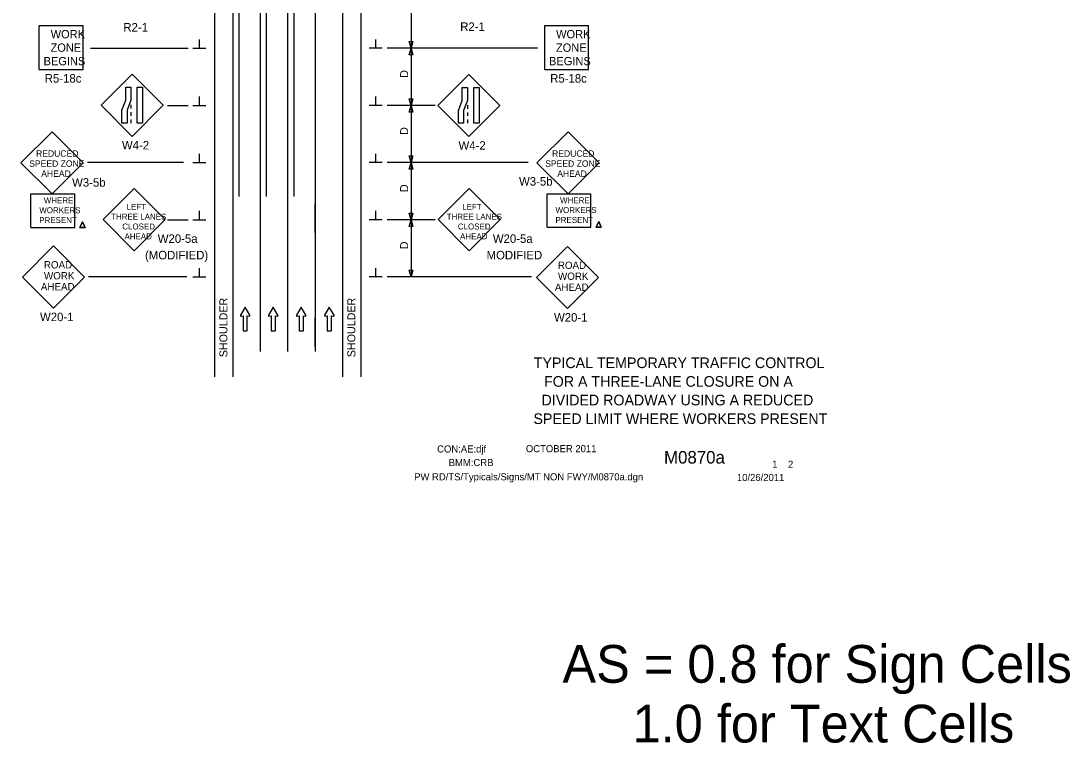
# Model space of a CAD drawing. Extents: x 16727 to 18475, y 5704 to 7011.
# Drawn here: x 16727 to 17644, y 5704 to 6336 of the extents above; entities that cross this region are included whole.
import ezdxf

# ---------------------------------------------------------------- set-up
doc = ezdxf.new("R2010")
doc.units = 0
for name, color, linetype in [('ALI_LEGAL_EX', 7, 'Continuous'), ('BORDER', 7, 'Continuous'), ('BORDER_SIGNAL_WO', 7, 'Continuous'), ('MT_SCRATCH_LEVEL_E', 7, 'Continuous'), ('PAVT_EDGE_EX', 7, 'Continuous'), ('TRAFFIC_SIGNS_PR', 7, 'Continuous'), ('TYPICAL_TEXT_DIMEN_PR', 7, 'Continuous')]:
    doc.layers.add(name, color=color, linetype=linetype)

msp = doc.modelspace()

# ---------------------------------------------------------------- linework, layer by layer
at = {"layer": 'ALI_LEGAL_EX'}
for p, q in [((16917.23, 7011.11), (16917.23, 6181.92)), ((16941.23, 7011.11), (16941.23, 6181.92)), ((16965.23, 7011.11), (16965.23, 6181.92)), ((16965.23, 7011.11), (16965.23, 6181.92)), ((16935.85, 6875.49), (16935.85, 6046.3)), ((16959.85, 6875.49), (16959.85, 6046.3)), ((16983.85, 6875.49), (16983.85, 6046.3)), ((16983.85, 6875.49), (16983.85, 6046.3))]:
    msp.add_line(p, q, dxfattribs=at)
for points in [[(16935.85, 6275.49), (16935.85, 6250.49)], [(16959.85, 6275.49), (16959.85, 6250.49)], [(16983.85, 6275.49), (16983.85, 6250.49)], [(16935.85, 6175.49), (16935.85, 6150.49)], [(16959.85, 6175.49), (16959.85, 6150.49)], [(16983.85, 6150.49), (16983.85, 6175.49)], [(16983.85, 6175.49), (16983.85, 6150.49)], [(16935.85, 6075.48), (16935.85, 6050.48)], [(16959.85, 6075.48), (16959.85, 6050.48)], [(16983.85, 6050.48), (16983.85, 6075.48)], [(16983.85, 6075.48), (16983.85, 6050.48)]]:
    msp.add_lwpolyline(points, dxfattribs=at)
at = {"layer": 'MT_SCRATCH_LEVEL_E'}
for p, q in [((16922.76, 6085.3), (16918.65, 6078.06)), ((16922.76, 6085.3), (16918.65, 6078.06)), ((16926.91, 6078.06), (16922.76, 6085.3)), ((16926.91, 6078.06), (16922.76, 6085.3)), ((16947.29, 6085.3), (16943.18, 6078.06)), ((16947.29, 6085.3), (16943.18, 6078.06)), ((16951.44, 6078.06), (16947.29, 6085.3)), ((16951.44, 6078.06), (16947.29, 6085.3)), ((16971.82, 6085.3), (16967.71, 6078.06)), ((16971.82, 6085.3), (16967.71, 6078.06)), ((16975.97, 6078.06), (16971.82, 6085.3)), ((16975.97, 6078.06), (16971.82, 6085.3)), ((16996.38, 6085.3), (16992.27, 6078.06)), ((16996.38, 6085.3), (16992.27, 6078.06)), ((17000.53, 6078.06), (16996.38, 6085.3)), ((17000.53, 6078.06), (16996.38, 6085.3)), ((16919.14, 6077.38), (16920.91, 6077.69)), ((16919.14, 6077.38), (16920.91, 6077.69)), ((16920.91, 6077.69), (16920.91, 6064.44)), ((16920.91, 6077.69), (16920.91, 6064.44)), ((16924.65, 6064.44), (16924.65, 6077.69)), ((16924.65, 6077.69), (16926.43, 6077.38)), ((16924.65, 6064.44), (16924.65, 6077.69)), ((16924.65, 6077.69), (16926.43, 6077.38)), ((16943.67, 6077.38), (16945.44, 6077.69)), ((16943.67, 6077.38), (16945.44, 6077.69)), ((16945.44, 6077.69), (16945.44, 6064.44)), ((16945.44, 6077.69), (16945.44, 6064.44)), ((16949.18, 6064.44), (16949.18, 6077.69)), ((16949.18, 6077.69), (16950.96, 6077.38)), ((16949.18, 6064.44), (16949.18, 6077.69)), ((16949.18, 6077.69), (16950.96, 6077.38)), ((16968.19, 6077.38), (16969.97, 6077.69)), ((16968.19, 6077.38), (16969.97, 6077.69)), ((16969.97, 6077.69), (16969.97, 6064.44)), ((16969.97, 6077.69), (16969.97, 6064.44)), ((16973.71, 6064.44), (16973.71, 6077.69)), ((16973.71, 6077.69), (16975.49, 6077.38)), ((16973.71, 6064.44), (16973.71, 6077.69)), ((16973.71, 6077.69), (16975.49, 6077.38)), ((16992.75, 6077.38), (16994.53, 6077.69)), ((16992.75, 6077.38), (16994.53, 6077.69)), ((16994.53, 6077.69), (16994.53, 6064.44)), ((16994.53, 6077.69), (16994.53, 6064.44)), ((16998.27, 6064.44), (16998.27, 6077.69)), ((16998.27, 6077.69), (17000.05, 6077.38)), ((16998.27, 6064.44), (16998.27, 6077.69)), ((16998.27, 6077.69), (17000.05, 6077.38)), ((16920.91, 6064.44), (16924.65, 6064.44)), ((16920.91, 6064.44), (16924.65, 6064.44)), ((16945.44, 6064.44), (16949.18, 6064.44)), ((16945.44, 6064.44), (16949.18, 6064.44)), ((16969.97, 6064.44), (16973.71, 6064.44)), ((16969.97, 6064.44), (16973.71, 6064.44)), ((16994.53, 6064.44), (16998.27, 6064.44)), ((16994.53, 6064.44), (16998.27, 6064.44))]:
    msp.add_line(p, q, dxfattribs=at)
for centre, start, end in [((16919.06, 6077.84), 150.42484, 279.96381), ((16919.06, 6077.84), 150.42484, 279.96381), ((16926.5, 6077.84), 260.03619, 29.77312), ((16926.5, 6077.84), 260.03619, 29.77312), ((16943.59, 6077.84), 150.42484, 279.96381), ((16943.59, 6077.84), 150.42484, 279.96381), ((16951.03, 6077.84), 260.03619, 29.77312), ((16951.03, 6077.84), 260.03619, 29.77312), ((16968.12, 6077.84), 150.42484, 279.96381), ((16968.12, 6077.84), 150.42484, 279.96381), ((16975.56, 6077.84), 260.03619, 29.77312), ((16975.56, 6077.84), 260.03619, 29.77312), ((16992.68, 6077.84), 150.42484, 279.96381), ((16992.68, 6077.84), 150.42484, 279.96381), ((17000.12, 6077.84), 260.03619, 29.77312), ((17000.12, 6077.84), 260.03619, 29.77312)]:
    msp.add_arc(centre, 0.463, start, end, dxfattribs=at)
at = {"layer": 'PAVT_EDGE_EX'}
for p, q in [((16911.85, 6920.73), (16911.85, 6024.13)), ((17007.85, 6920.73), (17007.85, 6024.13)), ((17023.85, 6920.73), (17023.85, 6024.13)), ((16895.85, 6869.12), (16895.85, 6024.13))]:
    msp.add_line(p, q, dxfattribs=at)
at = {"layer": 'TRAFFIC_SIGNS_PR'}
for p, q in [((16742.62, 6293.05), (16742.62, 6331.45)), ((16742.62, 6331.45), (16781.02, 6331.45)), ((16781.02, 6293.05), (16781.02, 6331.45)), ((17184.76, 6293.05), (17184.76, 6331.45)), ((17184.76, 6331.45), (17223.16, 6331.45)), ((17223.16, 6293.05), (17223.16, 6331.45)), ((16742.62, 6293.05), (16781.02, 6293.05)), ((16824, 6288.91), (16796.85, 6261.76)), ((16851.15, 6261.76), (16824, 6288.91)), ((17118.43, 6288.67), (17091.28, 6261.52)), ((17145.59, 6261.52), (17118.43, 6288.67)), ((17184.76, 6293.05), (17223.16, 6293.05)), ((16796.85, 6261.76), (16824, 6234.6)), ((16822.75, 6262.25), (16822.75, 6259.05)), ((16824, 6234.6), (16851.15, 6261.76)), ((17091.28, 6261.52), (17118.43, 6234.36)), ((17117.19, 6262.01), (17117.19, 6258.81)), ((17118.43, 6234.36), (17145.59, 6261.52)), ((16822.75, 6255.85), (16822.75, 6252.65)), ((16822.75, 6249.45), (16822.75, 6246.25)), ((17117.19, 6255.61), (17117.19, 6252.41)), ((17117.19, 6249.21), (17117.19, 6246.01)), ((16753.8, 6238.6), (16726.65, 6211.45)), ((16780.95, 6211.45), (16753.8, 6238.6)), ((17205.17, 6238.6), (17178.02, 6211.45)), ((17232.32, 6211.45), (17205.17, 6238.6)), ((16726.65, 6211.45), (16753.8, 6184.3)), ((16753.8, 6184.3), (16780.95, 6211.45)), ((17178.02, 6211.45), (17205.17, 6184.3)), ((17205.17, 6184.3), (17232.32, 6211.45)), ((16825.6, 6188.88), (16798.45, 6161.73)), ((16852.75, 6161.73), (16825.6, 6188.88)), ((17118.73, 6188.88), (17091.58, 6161.73)), ((17145.88, 6161.73), (17118.73, 6188.88)), ((16735.31, 6184.32), (16773.71, 6184.32)), ((16735.31, 6155), (16735.31, 6184.32)), ((16773.71, 6155), (16773.71, 6184.32)), ((17186.87, 6184.42), (17225.27, 6184.42)), ((17186.87, 6155.1), (17186.87, 6184.42)), ((17225.27, 6155.1), (17225.27, 6184.42)), ((16798.45, 6161.73), (16825.6, 6134.58)), ((16825.6, 6134.58), (16852.75, 6161.73)), ((17091.58, 6161.73), (17118.73, 6134.58)), ((17118.73, 6134.58), (17145.88, 6161.73)), ((16735.31, 6155), (16773.71, 6155)), ((17186.87, 6155.1), (17225.27, 6155.1)), ((16755.1, 6138.7), (16727.95, 6111.54)), ((16782.26, 6111.54), (16755.1, 6138.7)), ((17204.74, 6138.28), (17177.58, 6111.12)), ((17231.89, 6111.12), (17204.74, 6138.28)), ((16727.95, 6111.54), (16755.1, 6084.39)), ((16755.1, 6084.39), (16782.26, 6111.54)), ((17177.58, 6111.12), (17204.74, 6083.97)), ((17204.74, 6083.97), (17231.89, 6111.12))]:
    msp.add_line(p, q, dxfattribs=at)
for points in [[(16822.75, 6277.49), (16822.75, 6266.31), (16819.41, 6257.43), (16819.41, 6246.25), (16814.92, 6246.25), (16814.92, 6257.43), (16818.26, 6266.31), (16818.26, 6277.49)], [(16832.89, 6277.49), (16832.89, 6246.25), (16828.4, 6246.25), (16828.4, 6277.49)], [(17117.19, 6277.25), (17117.19, 6266.07), (17113.84, 6257.19), (17113.84, 6246.01), (17109.35, 6246.01), (17109.35, 6257.19), (17112.69, 6266.07), (17112.69, 6277.25)], [(17127.32, 6277.25), (17127.32, 6246.01), (17122.83, 6246.01), (17122.83, 6277.25)]]:
    msp.add_lwpolyline(points, close=True, dxfattribs=at)
for points in [[(16780.46, 6159.94), (16778.22, 6155)], [(16778.22, 6155), (16780.46, 6159.94)], [(16782.69, 6155), (16780.46, 6159.94)], [(16780.46, 6159.94), (16782.69, 6155)], [(17232.02, 6160.04), (17229.79, 6155.1)], [(17229.79, 6155.1), (17232.02, 6160.04)], [(17234.26, 6155.1), (17232.02, 6160.04)], [(17232.02, 6160.04), (17234.26, 6155.1)], [(16778.22, 6155), (16782.69, 6155)], [(16782.69, 6155), (16778.22, 6155)], [(17229.79, 6155.1), (17234.26, 6155.1)], [(17234.26, 6155.1), (17229.79, 6155.1)]]:
    msp.add_lwpolyline(points, dxfattribs=at)
at = {"layer": 'TYPICAL_TEXT_DIMEN_PR'}
for p, q in [((17067.85, 6361.65), (17067.85, 6311.65)), ((16882.73, 6311.65), (16882.73, 6319.43)), ((17036.98, 6311.65), (17036.98, 6319.43)), ((17067.85, 6311.65), (17066.28, 6317.51)), ((17066.28, 6317.51), (17067.85, 6317.51)), ((17067.85, 6317.51), (17069.42, 6317.51)), ((17069.42, 6317.51), (17067.85, 6311.65)), ((16787.54, 6311.65), (16872.85, 6311.65)), ((16877.1, 6311.65), (16888.35, 6311.65)), ((17042.6, 6311.65), (17031.35, 6311.65)), ((17178.58, 6311.65), (17046.85, 6311.65)), ((17066.28, 6305.79), (17067.85, 6311.65)), ((17067.85, 6305.79), (17066.28, 6305.79)), ((17067.85, 6311.65), (17069.42, 6305.79)), ((17067.85, 6311.65), (17067.85, 6261.65)), ((17069.42, 6305.79), (17067.85, 6305.79)), ((16882.73, 6261.65), (16882.73, 6269.43)), ((17036.98, 6261.65), (17036.98, 6269.43)), ((16854.78, 6261.65), (16872.85, 6261.65)), ((16877.1, 6261.65), (16888.35, 6261.65)), ((17042.6, 6261.65), (17031.35, 6261.65)), ((17089.07, 6261.65), (17046.85, 6261.65)), ((17067.85, 6261.65), (17066.28, 6267.51)), ((17066.28, 6267.51), (17067.85, 6267.51)), ((17066.28, 6255.79), (17067.85, 6261.65)), ((17067.85, 6267.51), (17069.42, 6267.51)), ((17069.42, 6267.51), (17067.85, 6261.65)), ((17067.85, 6261.65), (17067.85, 6211.65)), ((17067.85, 6261.65), (17069.42, 6255.79)), ((17067.85, 6255.79), (17066.28, 6255.79)), ((17069.42, 6255.79), (17067.85, 6255.79)), ((16882.73, 6211.65), (16882.73, 6219.43)), ((17036.98, 6211.65), (17036.98, 6219.43)), ((17067.85, 6211.65), (17066.28, 6217.51)), ((17066.28, 6217.51), (17067.85, 6217.51)), ((17067.85, 6217.51), (17069.42, 6217.51)), ((17069.42, 6217.51), (17067.85, 6211.65)), ((16868.8, 6211.65), (16784.7, 6211.65)), ((16877.1, 6211.65), (16888.35, 6211.65)), ((17042.6, 6211.65), (17031.35, 6211.65)), ((17170.25, 6211.65), (17046.85, 6211.65)), ((17066.28, 6205.79), (17067.85, 6211.65)), ((17067.85, 6205.79), (17066.28, 6205.79)), ((17067.85, 6211.65), (17067.85, 6161.65)), ((17067.85, 6211.65), (17069.42, 6205.79)), ((17069.42, 6205.79), (17067.85, 6205.79)), ((16882.73, 6161.65), (16882.73, 6169.43)), ((17036.98, 6161.65), (17036.98, 6169.43)), ((17067.85, 6161.65), (17066.28, 6167.51)), ((17066.28, 6167.51), (17067.85, 6167.51)), ((17067.85, 6167.51), (17069.42, 6167.51)), ((17069.42, 6167.51), (17067.85, 6161.65)), ((16854.78, 6161.65), (16872.85, 6161.65)), ((16877.1, 6161.65), (16888.35, 6161.65)), ((17042.6, 6161.65), (17031.35, 6161.65)), ((17089.07, 6161.65), (17046.85, 6161.65)), ((17066.28, 6155.79), (17067.85, 6161.65)), ((17067.85, 6161.65), (17067.85, 6111.65)), ((17067.85, 6161.65), (17069.42, 6155.79)), ((17067.85, 6155.79), (17066.28, 6155.79)), ((17069.42, 6155.79), (17067.85, 6155.79)), ((16871.85, 6111.65), (16785.72, 6111.65)), ((16877.1, 6111.65), (16888.35, 6111.65)), ((16882.73, 6111.65), (16882.73, 6119.43)), ((17042.6, 6111.65), (17031.35, 6111.65)), ((17036.98, 6111.65), (17036.98, 6119.43)), ((17173.3, 6111.65), (17046.85, 6111.65)), ((17067.85, 6111.65), (17066.28, 6117.51)), ((17066.28, 6117.51), (17067.85, 6117.51)), ((17067.85, 6117.51), (17069.42, 6117.51)), ((17069.42, 6117.51), (17067.85, 6111.65))]:
    msp.add_line(p, q, dxfattribs=at)

# ---------------------------------------------------------------- texts
at = {"layer": 'BORDER'}
for s, p in [('TYPICAL TEMPORARY TRAFFIC CONTROL', (17175.21, 6031.88)), (' FOR A THREE-LANE CLOSURE ON A ', (17180.75, 6015.58)), ('DIVIDED ROADWAY USING A REDUCED', (17182.02, 5999.28)), ('SPEED LIMIT WHERE WORKERS PRESENT', (17174.92, 5982.98))]:
    msp.add_text(s, height=9.3, dxfattribs=at).set_placement(p)
at = {"layer": 'BORDER_SIGNAL_WO'}
for s, height, p in [('CON:AE:djf', 6.2, (17090.69, 5958.06)), ('    OCTOBER 2011    ', 6.2, (17159.08, 5958.34)), ('    M0870a   ', 11, (17272.86, 5948.38)), ('BMM:CRB   ', 6.2, (17100.81, 5946.17)), (' 1    2 ', 6.2, (17381.45, 5944.7)), (' 1    2 ', 6.2, (17381.45, 5944.7)), ('PW RD/TS/Typicals/Signs/MT NON FWY/M0870a.dgn    ', 6.2, (17070.55, 5933.71)), ('10/26/2011    ', 6.2, (17352.93, 5933.13)), ('AS = 0.8 for Sign Cells', 33.0301, (17200.31, 5756.64)), ('     1.0 for Text Cells', 33.0301, (17200.31, 5704.41))]:
    msp.add_text(s, height=height, dxfattribs=at).set_placement(p)
at = {"layer": 'TRAFFIC_SIGNS_PR'}
for s, height, p in [('R2-1', 7.44, (16816.2, 6326.28)), ('R2-1', 7.44, (17110.85, 6326.86)), ('WORK', 7.217, (16752.62, 6320.42)), ('WORK', 7.217, (17194.76, 6320.42)), ('ZONE', 7.217, (16752.5, 6308.61)), ('ZONE', 7.217, (17194.64, 6308.61)), ('BEGINS', 7.217, (16746.43, 6296.8)), ('BEGINS', 7.217, (17188.57, 6296.8)), ('R5-18c', 7.44, (16747.43, 6281.61)), ('R5-18c', 7.44, (17189.57, 6281.61)), ('REDUCED', 5.6, (16739.86, 6216.76)), ('W4-2', 7.44, (16814.96, 6223.16)), ('W4-2', 7.44, (17109.39, 6222.92)), ('REDUCED', 5.6, (17191.23, 6216.76)), ('SPEED ZONE', 5.6, (16733.85, 6207.96)), ('SPEED ZONE', 5.6, (17185.22, 6207.96)), ('AHEAD', 5.6, (16744.41, 6199.16)), ('AHEAD', 5.6, (17195.78, 6199.16)), ('W3-5b', 7.44, (16771.35, 6190.57)), ('W3-5b', 7.44, (17162.33, 6191.52)), ('WHERE', 5.2, (16746.62, 6176)), ('WHERE', 5.2, (17198.18, 6176.11)), ('WORKERS', 5.2, (16742.69, 6167.4)), ('THREE LANES', 5.2, (16805.52, 6161.75)), ('LEFT', 5.2, (16819.08, 6170.35)), ('THREE LANES', 5.2, (17099.09, 6161.75)), ('LEFT', 5.2, (17112.64, 6170.35)), ('WORKERS', 5.2, (17194.26, 6167.51)), ('PRESENT', 5.2, (16742.62, 6158.8)), ('CLOSED', 5.2, (16815.25, 6153.15)), ('CLOSED', 5.2, (17108.82, 6153.15)), ('PRESENT', 5.2, (17194.19, 6158.91)), ('AHEAD', 5.2, (16817.2, 6144.55)), ('W20-5a', 7.44, (16846.29, 6141.43)), ('AHEAD', 5.2, (17110.76, 6144.55)), ('W20-5a', 7.44, (17139.42, 6141.42)), ('(MODIFIED)', 7.44, (16835.14, 6126.99)), ('MODIFIED', 7.44, (17133.93, 6126.98)), ('ROAD', 6.4, (16746.65, 6119.08)), ('ROAD', 6.4, (17196.28, 6118.66)), ('WORK', 6.4, (16746.75, 6109.48)), ('WORK', 6.4, (17196.39, 6109.06)), ('AHEAD', 6.4, (16744.06, 6099.88)), ('AHEAD', 6.4, (17193.7, 6099.46)), ('W20-1', 7.44, (16743.27, 6072.95)), ('W20-1', 7.44, (17192.91, 6072.53))]:
    msp.add_text(s, height=height, dxfattribs=at).set_placement(p)
at = {"layer": 'TYPICAL_TEXT_DIMEN_PR'}
for s, p in [('D', (17065.3, 6285.87)), ('D', (17065.3, 6235.87)), ('D', (17065.3, 6185.87)), ('D', (17065.3, 6135.87)), ('SHOULDER', (16907.23, 6041.41)), ('SHOULDER', (17019.14, 6041.41))]:
    msp.add_text(s, height=7, rotation=90, dxfattribs=at).set_placement(p)

doc.saveas('drawing.dxf')
